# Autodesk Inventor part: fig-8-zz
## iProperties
Created: 2009-04
Part Number: fig-8-zz
Document SubType Name: Modeling
Designer: Sham
Density: 1 g/cm^3
Author: Sham
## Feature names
1. Extrusion2
2. Split8
